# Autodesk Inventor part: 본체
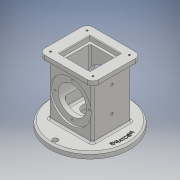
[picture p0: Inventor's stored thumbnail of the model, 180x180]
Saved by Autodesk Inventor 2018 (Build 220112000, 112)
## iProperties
Created: 2019-08
Part Number: 본체
Material: 일반
Document SubType Name: Modeling
Designer: USER
Density: 1 g/cm^3
Appearance: 기본값
Mass: 386.636 g
Surface Area: 791.142 cm^2
Volume: 386.636 cm^3
Author: USER
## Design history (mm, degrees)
sketch "스케치2"
  geometry: C1 r 67.5 at (0, 0); 1 further point
  constraints: 1 centre point, 1 coincident
  dimensions: "d1" = 135 diameter of C1
extrude "돌출1" new body sketch "스케치2" distance "d2" = 10; taper "d3" = 0 deg
sketch "스케치3" dims "d4" = 118
  geometry: C1 r 4.5 at (0, 59); 2 further points
  constraints: 2 vertical alignment, 1 centre point, 1 coincident, 2 other
  dimensions: "d5" = 9 diameter of C1
extrude "돌출2" cut sketch "스케치3" extent not by distance; stored distance "d6" = 10; taper "d7" = 0 deg
sketch "스케치4" dims "d11" = 118
  geometry: C1 r 4.5 at (-59, 0); 2 further points
  constraints: 2 horizontal alignment, 1 centre point, 1 coincident, 2 other
  dimensions: "d12" = 9 diameter of C1
extrude "돌출3" cut sketch "스케치4" extent not by distance; stored distance "d13" = 10; taper "d14" = 0 deg
sketch "스케치5"
  geometry: L1 (37, -33)-(-37, -33); L2 (-37, -33)-(-37, 33); L3 (-37, 33)-(37, 33); L4 (37, 33)-(37, -33); L5 (37, -33)-(-37, 33); L6 (-37, -33)-(37, 33); 1 further point
  constraints: 12 end point, 2 midpoint, 2 parallel, 1 horizontal, 1 perpendicular
  dimensions: "d15" = 74 distance of L2.end L3.end; "d16" = 66 distance of L1.end L2.end
extrude "돌출4" join sketch "스케치5" distance "d17" = 88; taper "d18" = 0 deg
node "스케치6"
sketch "스케치7"
  geometry: L1 (46, -41)-(-46, -41); L2 (-46, -41)-(-46, 41); L3 (-46, 41)-(46, 41); L4 (46, 41)-(46, -41); L5 (46, -41)-(-46, 41); L6 (-46, -41)-(46, 41); 1 further point
  constraints: 12 end point, 2 midpoint, 2 parallel, 1 horizontal, 1 perpendicular
  dimensions: "d19" = 92 distance of L2.end L3.end; "d20" = 82 distance of L1.end L2.end
extrude "돌출5" join sketch "스케치7" distance "d21" = 10; taper "d22" = 0 deg
sketch "스케치8"
  geometry: L1 (-30.5, -10)-(104.5, -10) reference; C1 r 35 at (37, 44); 2 further points
  constraints: 1 centre point, 1 midpoint, 1 vertical alignment
  dimensions: "d23" = 70 diameter of C1; "d24" = 54 distance from line of L1 C1.centre
extrude "돌출6" cut sketch "스케치8" distance "d25" = 3; taper "d26" = 0 deg
sketch "스케치9"
  geometry: C1 r 24 at (0, 0); C2 r 35 at (0, 0) reference; 1 further point
  constraints: 1 centre point, 1 concentric
  dimensions: "d27" = 48 diameter of C1
extrude "돌출7" cut sketch "스케치9" extent not by distance; stored distance "d28" = 3; taper "d29" = 0 deg
sketch "스케치10" dims "d30" = 58
  geometry: C1 r 35 at (0, 0) reference; 3 further points
  constraints: 2 vertical alignment, 3 other
hole "구멍1" sketch "스케치10" at (0, 29) diameter "d31" = 3.242; stored, may be unused: countersink angle "d35" = 90 deg, drill point angle "d37" = 118 deg; dims "d32" = 4, "d33" = 4, "d34" = 2, "d36" = 6
sketch "스케치11"
  geometry: L1 (26, -26)-(-26, -26); L2 (-26, -26)-(-26, 26); L3 (-26, 26)-(26, 26); L4 (26, 26)-(26, -26); L5 (26, -26)-(-26, 26); L6 (-26, -26)-(26, 26); 1 further point
  constraints: 12 end point, 2 midpoint, 2 parallel, 1 horizontal, 1 perpendicular
  dimensions: "d41" = 52 distance of L2.end L3.end; "d42" = 52 distance of L1.end L2.end
extrude "돌출8" cut sketch "스케치11" distance "d43" = 8; taper "d44" = 0 deg
sketch "스케치12"
  geometry: L1 (-22, -22)-(22, -22); L2 (22, -22)-(22, 22); L3 (22, 22)-(-22, 22); L4 (-22, 22)-(-22, -22); L5 (-22, -22)-(22, 22); L6 (22, -22)-(-22, 22); 1 further point
  constraints: 12 end point, 2 midpoint, 2 parallel, 1 horizontal, 1 perpendicular
  dimensions: "d45" = 44 distance of L2.end L3.end; "d46" = 44 distance of L3.end L1.start
extrude "돌출9" cut sketch "스케치12" distance "d47" = 74; taper "d48" = 0 deg
sketch "스케치13"
  geometry: C1 r 25 at (0, 0); C2 r 67.5 at (0, 0) reference; 1 further point
  constraints: 1 centre point, 1 coincident, 1 concentric
  dimensions: "d49" = 50 diameter of C1
extrude "돌출10" cut sketch "스케치13" distance "d50" = 18; taper "d51" = 0 deg
sketch "스케치14"
  geometry: C1 r 12.5 at (0, 0); C2 r 25 at (0, 0) reference; 1 further point
  constraints: 1 centre point, 1 coincident, 1 concentric
  dimensions: "d52" = 25 diameter of C1
extrude "돌출11" cut sketch "스케치14" extent not by distance; stored distance "d53" = 18; taper "d54" = 0 deg
fillet "모깎기1" dims "d55" = 3
chamfer "모따기1" distance "d56" = 1; stored, may be unused: second distance "d57" = 2, angle "d58" = 45 deg
fillet "모깎기2" dims "d59" = 3
fillet "모깎기3" dims "d60" = 3
fillet "모깎기4" dims "d61" = 10
fillet "모깎기5" dims "d62" = 3
fillet "모깎기6" dims "d63" = 3
sketch "스케치15"
  geometry: L1 (36, -31)-(-36, -31); L2 (-36, -31)-(-36, 31); L3 (-36, 31)-(36, 31); L4 (36, 31)-(36, -31); L5 (36, -31)-(-36, 31); L6 (-36, -31)-(36, 31); C1 r 25 at (0, 0) reference; 5 further points
  constraints: 12 end point, 4 coincident, 2 midpoint, 2 parallel, 1 horizontal, 1 perpendicular
  dimensions: "d64" = 72 distance of L2.end L3.end; "d65" = 62 distance of L3.end L1.start
hole "구멍2" sketch "스케치15" at (-36, 31), (-36, -31), (36, -31), (36, 31) diameter "d66" = 3.242; stored, may be unused: countersink angle "d70" = 90 deg, drill point angle "d72" = 118 deg; dims "d67" = 4, "d68" = 4, "d69" = 2, "d71" = 6
sketch "스케치16"
  geometry: L1 (13, -37.5)-(13, 97.5) reference; 3 further points
  constraints: 2 horizontal alignment
  dimensions: "d73" = 37 distance from line of point (-24, 30) L1; "d74" = 43 distance of point (-67, 30) point (-24, 30)
hole "구멍3" sketch "스케치16" at (-67, 30), (-24, 30) diameter "d75" = 4.917; stored, may be unused: countersink angle "d79" = 90 deg, drill point angle "d81" = 118 deg; dims "d76" = 28, "d77" = 4, "d78" = 2, "d80" = 30
fillet "모깎기7" dims "d82" = 3
sketch "스케치17"
  geometry: C1 r 59 at (0, 0); 1 further point
  constraints: 1 centre point, 1 coincident, 1 other
  dimensions: "d83" = 118 diameter of C1
feature "엠보싱1" sketch "스케치17" dims "d84" = 0.5, "d85" = 0
chamfer "모따기2" distance "d86" = 3; stored, may be unused: second distance "d87" = 2, angle "d88" = 45 deg
node "솔리드1"
mirror "미러1"
pattern_circular "원형 패턴2" dims angle "d39" = 360 deg
mirror "미러2"
